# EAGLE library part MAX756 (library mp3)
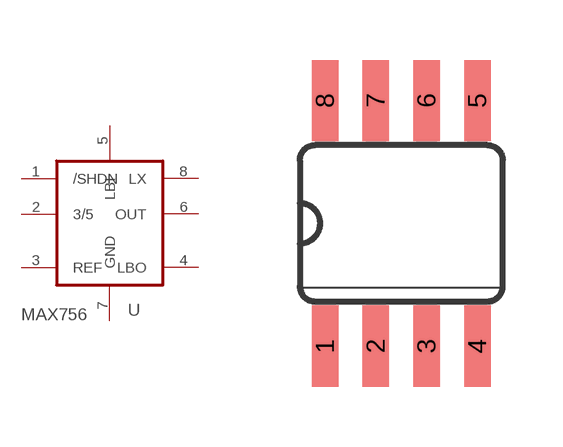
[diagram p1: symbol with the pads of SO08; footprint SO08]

Designator prefix -

## MAX756SOIC  [SO08]
1  /SHDN  in
2  3/5
3  REF  pas
4  LBO  in
5  LBI  in
6  OUT  out
7  GND  pwr
8  LX  out

## Footprint SO08 (pad centres in mm)
smd 0.66 x 2.032: 1 -1.905,-3.073; 2 -0.635,-3.073; 3 0.635,-3.073; 4 1.905,-3.073; 5 1.905,3.073; 6 0.635,3.073; 7 -0.635,3.073; 8 -1.905,3.073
